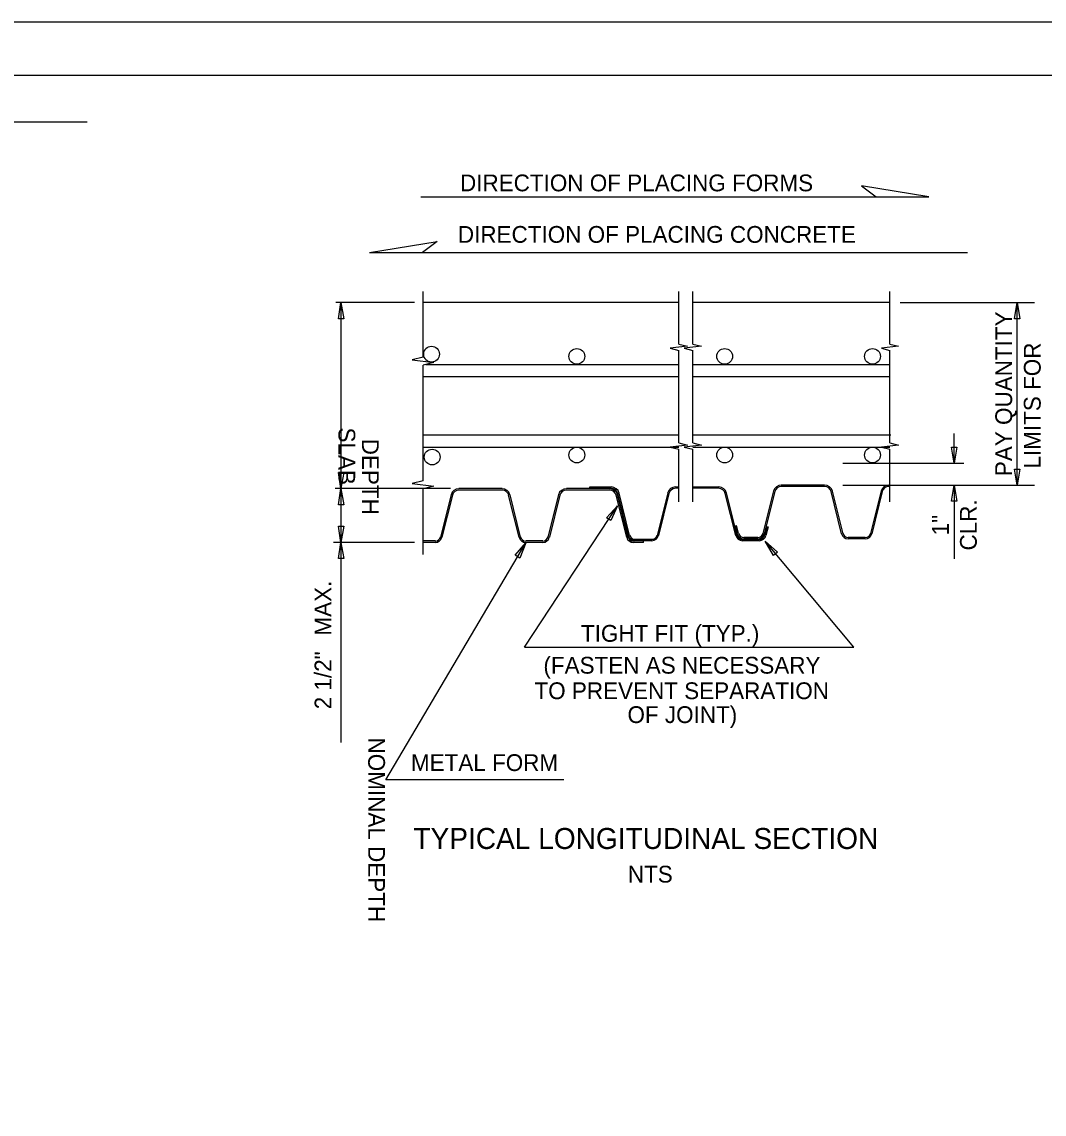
# Model space of a CAD drawing. Extents: x 0 to 34, y 0 to 23.5.
# Drawn here: x 14.51 to 24.1, y 11.76 to 22 of the extents above; entities that cross this region are included whole.
import ezdxf

# ---------------------------------------------------------------- set-up
doc = ezdxf.new("R2010")
doc.units = 0
for name, color, linetype in [('BORDER_ANNO_Cutsheet', 7, 'Continuous'), ('BRDG_ANNO_Anno-Sheet', 7, 'Continuous'), ('BRDG_ANNO_General-Notes', 7, 'Continuous'), ('BRDG_BASE_Obj-Line', 7, 'Continuous'), ('BRDG_BASE_Rebar', 7, 'Continuous')]:
    doc.layers.add(name, color=color, linetype=linetype)

msp = doc.modelspace()

# ---------------------------------------------------------------- linework, layer by layer
at = {"layer": 'BORDER_ANNO_Cutsheet'}
msp.add_lwpolyline([(0, 22), (34, 22), (34, 0), (0, 0)], close=True, dxfattribs=at)
at = {"layer": 'BRDG_ANNO_Anno-Sheet'}
msp.add_lwpolyline([(1.5, 21.5), (33.5, 21.5), (33.5, 0.5), (1.5, 0.5)], close=True, dxfattribs=at)
at = {"layer": 'BRDG_ANNO_General-Notes'}
for p, q in [((1.917, 21.061), (15.124, 21.061)), ((18.252, 20.359), (23.016, 20.359)), ((17.772, 19.838), (23.379, 19.838)), ((18.193, 19.367), (17.457, 19.367)), ((17.48, 19.215), (17.504, 19.367)), ((17.504, 19.367), (17.504, 17.623)), ((17.504, 19.367), (17.53, 19.215)), ((22.747, 19.367), (24.006, 19.367)), ((23.817, 19.216), (23.843, 19.367)), ((23.843, 17.655), (23.843, 19.367)), ((23.843, 19.367), (23.867, 19.216)), ((17.53, 19.215), (17.48, 19.215)), ((23.867, 19.216), (23.817, 19.216)), ((23.252, 17.862), (23.252, 18.139)), ((23.227, 18.013), (23.277, 18.013)), ((23.252, 17.862), (23.227, 18.013)), ((23.277, 18.013), (23.252, 17.862)), ((22.208, 17.862), (23.342, 17.862)), ((17.48, 17.774), (17.53, 17.774)), ((17.504, 17.623), (17.48, 17.774)), ((17.53, 17.774), (17.504, 17.623)), ((23.817, 17.807), (23.867, 17.807)), ((23.843, 17.655), (23.817, 17.807)), ((23.867, 17.807), (23.843, 17.655)), ((18.531, 17.623), (17.449, 17.623)), ((17.48, 17.471), (17.504, 17.623)), ((17.504, 17.623), (17.504, 17.119)), ((17.504, 17.623), (17.53, 17.471)), ((22.208, 17.655), (24.006, 17.655)), ((23.227, 17.505), (23.252, 17.655)), ((23.252, 17.655), (23.252, 16.966)), ((23.252, 17.655), (23.277, 17.505)), ((17.53, 17.471), (17.48, 17.471)), ((19.223, 16.136), (20.095, 17.462)), ((19.992, 17.35), (20.095, 17.462)), ((20.095, 17.462), (20.033, 17.323)), ((23.277, 17.505), (23.227, 17.505)), ((20.033, 17.323), (19.992, 17.35)), ((17.48, 17.27), (17.53, 17.27)), ((17.504, 17.119), (17.48, 17.27)), ((17.53, 17.27), (17.504, 17.119)), ((18.193, 17.119), (17.435, 17.119)), ((17.48, 16.967), (17.504, 17.119)), ((17.504, 17.119), (17.504, 15.241)), ((17.504, 17.119), (17.53, 16.967)), ((17.925, 14.891), (19.236, 17.116)), ((19.138, 16.998), (19.236, 17.116)), ((19.236, 17.116), (19.181, 16.972)), ((22.311, 16.136), (21.481, 17.129)), ((21.559, 16.997), (21.481, 17.129)), ((21.481, 17.129), (21.598, 17.028)), ((21.598, 17.028), (21.559, 16.997)), ((17.53, 16.967), (17.48, 16.967)), ((19.181, 16.972), (19.138, 16.998)), ((19.223, 16.136), (22.311, 16.136)), ((19.594, 14.891), (17.925, 14.891))]:
    msp.add_line(p, q, dxfattribs=at)
for points in [[(23.016, 20.359), (22.383, 20.463), (22.52, 20.359)], [(17.772, 19.838), (18.405, 19.94), (18.268, 19.838)]]:
    msp.add_lwpolyline(points, dxfattribs=at)
at = {"layer": 'BRDG_BASE_Obj-Line'}
for p, q in [((18.274, 18.856), (18.274, 19.473)), ((20.672, 18.979), (20.672, 19.473)), ((20.803, 18.979), (20.803, 19.473)), ((22.651, 18.979), (22.651, 19.473)), ((20.672, 19.367), (18.274, 19.367)), ((22.651, 19.367), (20.803, 19.367)), ((20.753, 18.959), (20.591, 18.939)), ((20.672, 18.979), (20.753, 18.959)), ((20.883, 18.959), (20.722, 18.939)), ((20.803, 18.979), (20.883, 18.959)), ((22.732, 18.959), (22.57, 18.939)), ((22.651, 18.979), (22.732, 18.959)), ((18.274, 18.856), (18.172, 18.83)), ((20.591, 18.939), (20.672, 18.919)), ((20.672, 18.052), (20.672, 18.919)), ((20.722, 18.939), (20.803, 18.919)), ((20.803, 18.052), (20.803, 18.919)), ((22.57, 18.939), (22.651, 18.919)), ((22.651, 18.052), (22.651, 18.919)), ((18.172, 18.83), (18.374, 18.806)), ((18.374, 18.806), (18.274, 18.78)), ((18.274, 17.697), (18.274, 18.78)), ((20.753, 18.032), (20.591, 18.011)), ((20.672, 18.052), (20.753, 18.032)), ((20.883, 18.032), (20.722, 18.011)), ((20.803, 18.052), (20.883, 18.032)), ((22.732, 18.032), (22.57, 18.011)), ((22.651, 18.052), (22.732, 18.032)), ((20.591, 18.011), (20.672, 17.992)), ((20.672, 17.498), (20.672, 17.992)), ((20.722, 18.011), (20.803, 17.992)), ((20.803, 17.498), (20.803, 17.992)), ((22.57, 18.011), (22.651, 17.992)), ((22.651, 17.498), (22.651, 17.992)), ((18.274, 17.697), (18.172, 17.672)), ((18.172, 17.672), (18.374, 17.646)), ((18.374, 17.646), (18.274, 17.622)), ((18.274, 17.004), (18.274, 17.622)), ((18.812, 17.623), (18.609, 17.623)), ((19.015, 17.623), (18.812, 17.623)), ((19.82, 17.623), (19.617, 17.623)), ((20.022, 17.623), (19.82, 17.623)), ((20.038, 17.638), (19.835, 17.638)), ((19.835, 17.638), (19.835, 17.626)), ((20.038, 17.626), (19.835, 17.626)), ((20.672, 17.638), (20.64, 17.638)), ((20.672, 17.626), (20.64, 17.626)), ((20.843, 17.638), (20.803, 17.638)), ((20.843, 17.626), (20.803, 17.626)), ((21.046, 17.638), (20.843, 17.638)), ((21.046, 17.626), (20.843, 17.626)), ((21.835, 17.655), (21.632, 17.655)), ((21.835, 17.643), (21.632, 17.643)), ((22.038, 17.655), (21.835, 17.655)), ((22.038, 17.643), (21.835, 17.643)), ((22.651, 17.655), (22.64, 17.655)), ((22.651, 17.643), (22.64, 17.643)), ((18.536, 17.566), (18.436, 17.167)), ((18.548, 17.563), (18.45, 17.167)), ((18.812, 17.61), (18.609, 17.61)), ((19.015, 17.61), (18.812, 17.61)), ((19.175, 17.167), (19.076, 17.563)), ((19.188, 17.167), (19.089, 17.566)), ((19.544, 17.566), (19.444, 17.167)), ((19.556, 17.563), (19.458, 17.167)), ((19.82, 17.61), (19.617, 17.61)), ((20.022, 17.61), (19.82, 17.61)), ((20.183, 17.167), (20.083, 17.563)), ((20.196, 17.167), (20.096, 17.566)), ((20.198, 17.182), (20.099, 17.578)), ((20.21, 17.182), (20.111, 17.581)), ((20.567, 17.581), (20.467, 17.182)), ((20.579, 17.578), (20.48, 17.182)), ((21.205, 17.182), (21.107, 17.578)), ((21.218, 17.182), (21.119, 17.581)), ((21.56, 17.601), (21.46, 17.203)), ((21.571, 17.595), (21.473, 17.2)), ((22.198, 17.2), (22.099, 17.595)), ((22.211, 17.2), (22.111, 17.598)), ((22.567, 17.601), (22.468, 17.203)), ((22.579, 17.595), (22.481, 17.2)), ((21.213, 17.275), (21.201, 17.272)), ((21.219, 17.2), (21.201, 17.272)), ((21.232, 17.203), (21.213, 17.275)), ((21.496, 17.267), (21.475, 17.182)), ((21.508, 17.265), (21.488, 17.182)), ((21.496, 17.267), (21.508, 17.265)), ((18.389, 17.132), (18.274, 17.132)), ((18.389, 17.119), (18.274, 17.119)), ((19.316, 17.132), (19.236, 17.132)), ((19.316, 17.119), (19.236, 17.119)), ((19.397, 17.132), (19.316, 17.132)), ((19.397, 17.119), (19.316, 17.119)), ((20.339, 17.132), (20.244, 17.132)), ((20.339, 17.119), (20.244, 17.119)), ((20.339, 17.147), (20.259, 17.147)), ((20.339, 17.135), (20.259, 17.135)), ((20.419, 17.147), (20.339, 17.147)), ((20.419, 17.135), (20.339, 17.135)), ((20.339, 17.119), (20.339, 17.132)), ((21.347, 17.147), (21.266, 17.147)), ((21.347, 17.135), (21.266, 17.135)), ((21.347, 17.164), (21.28, 17.164)), ((21.347, 17.151), (21.28, 17.151)), ((21.411, 17.164), (21.347, 17.164)), ((21.411, 17.151), (21.347, 17.151)), ((21.427, 17.147), (21.347, 17.147)), ((21.427, 17.135), (21.347, 17.135)), ((22.339, 17.164), (22.259, 17.164)), ((22.339, 17.151), (22.259, 17.151)), ((22.419, 17.164), (22.339, 17.164)), ((22.419, 17.151), (22.339, 17.151))]:
    msp.add_line(p, q, dxfattribs=at)
for centre, radius, start, end in [((18.61, 17.547), 0.0756, 90, 166.0367), ((19.015, 17.547), 0.0756, 13.9633, 90), ((19.617, 17.547), 0.0756, 90, 166.0367), ((20.023, 17.547), 0.0756, 13.9633, 90), ((20.038, 17.563), 0.0756, 13.9633, 90), ((20.038, 17.563), 0.063, 13.9633, 90), ((20.64, 17.563), 0.0756, 89.7446, 166.0367), ((20.64, 17.563), 0.063, 90, 166.0367), ((21.046, 17.563), 0.0756, 13.9633, 90), ((21.046, 17.563), 0.063, 13.9633, 90), ((21.633, 17.58), 0.0756, 90, 166.0367), ((21.633, 17.58), 0.063, 90, 166.0367), ((22.038, 17.58), 0.0756, 13.9633, 90), ((22.038, 17.58), 0.063, 13.9633, 90), ((22.64, 17.58), 0.0748, 90, 164.1569), ((22.64, 17.58), 0.063, 90.1763, 166.0367), ((18.61, 17.547), 0.063, 90, 166.0367), ((19.015, 17.547), 0.063, 13.9633, 90), ((19.617, 17.547), 0.063, 90, 166.0367), ((20.023, 17.547), 0.063, 13.9633, 90), ((18.388, 17.182), 0.0504, 270, 345.9547), ((18.388, 17.182), 0.063, 270, 345.9547), ((19.236, 17.182), 0.063, 193.9933, 270), ((19.236, 17.182), 0.0504, 193.9933, 270), ((19.396, 17.182), 0.0504, 270, 345.9547), ((19.396, 17.182), 0.063, 270, 345.9547), ((20.244, 17.182), 0.063, 193.9933, 270), ((20.244, 17.182), 0.0504, 193.9933, 270), ((20.259, 17.198), 0.063, 193.9933, 270), ((20.259, 17.198), 0.0504, 193.9933, 270), ((20.419, 17.198), 0.0504, 270, 345.9547), ((20.419, 17.198), 0.063, 270, 345.9547), ((21.267, 17.198), 0.063, 193.9933, 270), ((21.267, 17.198), 0.0504, 193.9933, 270), ((21.281, 17.215), 0.063, 193.9933, 270), ((21.281, 17.215), 0.0504, 193.9933, 270), ((21.411, 17.215), 0.0504, 270, 345.9547), ((21.411, 17.215), 0.063, 270, 345.9547), ((21.427, 17.198), 0.0504, 270, 345.9547), ((21.427, 17.198), 0.063, 270, 345.9547), ((22.259, 17.215), 0.063, 193.9933, 270), ((22.259, 17.215), 0.0504, 193.9933, 270), ((22.419, 17.215), 0.0504, 270, 345.9547), ((22.419, 17.215), 0.063, 270, 345.9547)]:
    msp.add_arc(centre, radius, start, end, dxfattribs=at)
at = {"layer": 'BRDG_BASE_Rebar'}
for p, q in [((18.3, 18.787), (20.672, 18.787)), ((20.803, 18.787), (22.651, 18.787)), ((18.274, 18.674), (20.672, 18.674)), ((20.803, 18.674), (22.651, 18.674)), ((18.274, 18.127), (20.672, 18.127)), ((20.803, 18.127), (22.658, 18.127)), ((18.274, 18.013), (20.672, 18.013)), ((20.803, 18.013), (22.651, 18.013))]:
    msp.add_line(p, q, dxfattribs=at)
for centre in [(18.353, 18.884), (19.715, 18.863), (21.101, 18.863), (22.487, 18.863), (18.359, 17.919), (19.715, 17.938), (21.101, 17.938), (22.487, 17.938)]:
    msp.add_circle(centre, 0.0738, dxfattribs=at)

# ---------------------------------------------------------------- texts
at = {"layer": 'BRDG_ANNO_General-Notes'}
for s, height, p in [('DIRECTION OF PLACING FORMS', 0.15745, (18.62, 20.411)), ('DIRECTION OF PLACING CONCRETE ', 0.15745, (18.6, 19.928)), ('TIGHT FIT (TYP.)', 0.15745, (19.754, 16.187)), ('(FASTEN AS NECESSARY', 0.15745, (19.402, 15.888)), ('TO PREVENT SEPARATION', 0.15745, (19.318, 15.649)), ('OF JOINT)', 0.1574, (20.19, 15.425)), ('METAL FORM', 0.1574, (18.16, 14.975)), ('TYPICAL LONGITUDINAL SECTION', 0.19681, (18.183, 14.244)), ('NTS', 0.1575, (20.193, 13.929))]:
    msp.add_text(s, height=height, dxfattribs=at).set_placement(p)
for s, height, rotation, p in [('PAY QUANTITY', 0.15746, 90, (23.796, 17.74)), ('LIMITS FOR', 0.1575, 90, (24.064, 17.811)), ('SLAB ', 0.1574, 270, (17.48, 18.196)), ('DEPTH', 0.1574, 270, (17.701, 18.091)), ('CLR.', 0.1574, 90, (23.465, 17.043)), ('1"', 0.1574, 90, (23.203, 17.185)), ('MAX.', 0.1574, 90, (17.414, 16.245)), ('2 1/2"', 0.1574, 90, (17.414, 15.554)), ('NOMINAL DEPTH', 0.15745, 270, (17.759, 15.289))]:
    msp.add_text(s, height=height, rotation=rotation, dxfattribs=at).set_placement(p)

doc.saveas('drawing.dxf')
